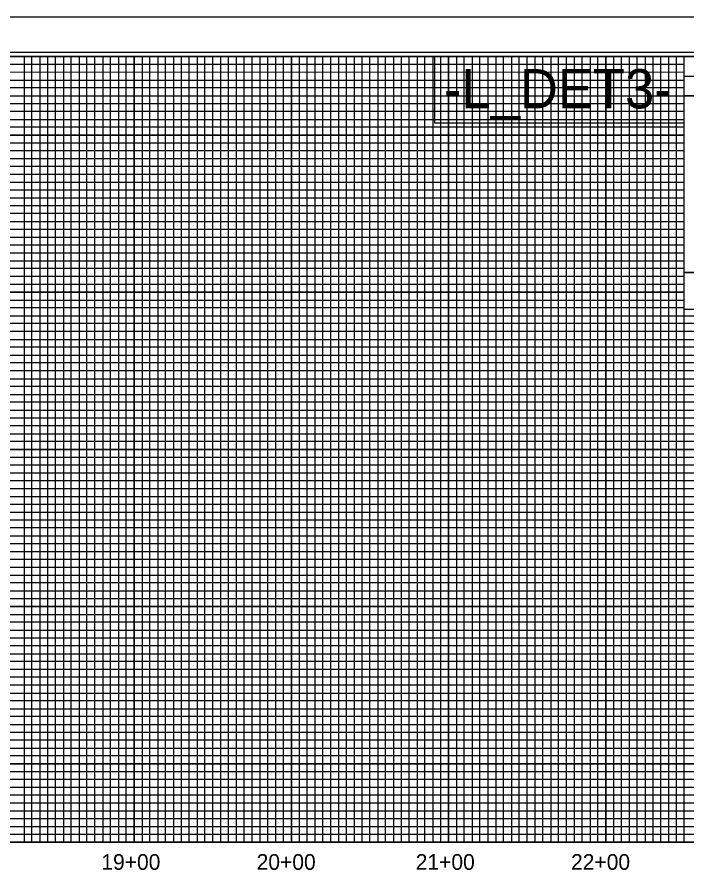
# Model space of a CAD drawing. Extents: x 497599 to 513368, y 404140 to 476034.
# Drawn here: x 506734 to 507160, y 439315 to 439861 of the extents above; entities that cross this region are included whole.
import ezdxf

# ---------------------------------------------------------------- set-up
doc = ezdxf.new("R2010")
doc.units = 0
for name, color, linetype in [('Exist Vertical Profile Vertical Axis Label', 7, 'Continuous'), ('Old_Level_1', 7, 'Continuous'), ('Prop Grid Mask', 7, 'Continuous'), ('Sheet Cutting Line CELL', 7, 'Continuous'), ('Sheet DOT Grid CELL', 7, 'Continuous'), ('Sheet Layout Profile Border Port 2', 7, 'Continuous'), ('Sheet Plot Border Inside CELL', 7, 'Continuous'), ('Sheet Plot Border Outside CELL', 7, 'Continuous'), ('Sheet Profile CELL', 7, 'Continuous'), ('Sheet Profile Grid Major CELL', 7, 'Continuous'), ('Sheet Profile Grid Middle CELL', 7, 'Continuous'), ('Sheet Profile Grid Minor CELL', 7, 'Continuous'), ('Sheet Sticker Exception Certification CELL', 7, 'Continuous')]:
    doc.layers.add(name, color=color, linetype=linetype)

msp = doc.modelspace()

# ---------------------------------------------------------------- linework, layer by layer
at = {"layer": 'Prop Grid Mask'}
msp.add_lwpolyline([(507158.63, 439836.14), (506999.77, 439836.14), (506999.77, 439793.82), (507158.63, 439793.82)], close=True, dxfattribs=at)
at = {"layer": 'Sheet Cutting Line CELL'}
msp.add_line((507375.68, 439861.14), (505691.68, 439861.14), dxfattribs=at)
at = {"layer": 'Sheet DOT Grid CELL'}
for p, q in [((506758.68, 439336.14), (506758.68, 439836.14)), ((506808.68, 439336.14), (506808.68, 439836.14)), ((506858.68, 439336.14), (506858.68, 439836.14)), ((506908.68, 439336.14), (506908.68, 439836.14)), ((506958.68, 439336.14), (506958.68, 439836.14)), ((507008.68, 439336.14), (507008.68, 439836.14)), ((507058.68, 439336.14), (507058.68, 439836.14)), ((507108.68, 439336.14), (507108.68, 439836.14)), ((507158.63, 439786.14), (505858.68, 439786.14)), ((507158.63, 439736.14), (505858.68, 439736.14)), ((507158.68, 439336.14), (507158.68, 439698.59)), ((507158.68, 439686.14), (505858.68, 439686.14)), ((507358.68, 439636.14), (505858.68, 439636.14)), ((507358.68, 439586.14), (505858.68, 439586.14)), ((507358.68, 439536.14), (505858.68, 439536.14)), ((507358.68, 439486.14), (505858.68, 439486.14)), ((507358.68, 439436.14), (505858.68, 439436.14)), ((507358.68, 439386.14), (505858.68, 439386.14))]:
    msp.add_line(p, q, dxfattribs=at)
at = {"layer": 'Sheet Layout Profile Border Port 2'}
msp.add_lwpolyline([(505908.68, 439836.14), (507308.68, 439836.14), (507308.68, 439336.14), (505908.68, 439336.14)], close=True, dxfattribs=at)
at = {"layer": 'Sheet Plot Border Inside CELL'}
msp.add_lwpolyline([(505704.68, 438783.59), (507371.18, 438783.59), (507371.18, 439838.69), (505704.68, 439838.69)], close=True, dxfattribs=at)
at = {"layer": 'Sheet Plot Border Outside CELL'}
msp.add_lwpolyline([(505691.68, 438761.14), (507375.68, 438761.14), (507375.68, 439861.14), (505691.68, 439861.14)], close=True, dxfattribs=at)
at = {"layer": 'Sheet Profile CELL'}
for p, q in [((507158.63, 439823.59), (507358.68, 439823.59)), ((505858.68, 439336.14), (507358.68, 439336.14))]:
    msp.add_line(p, q, dxfattribs=at)
for points in [[(507358.68, 439836.14), (505858.68, 439836.14), (505858.68, 438786.14), (507358.68, 438786.14)], [(507158.63, 439836.14), (507358.68, 439836.14), (507358.68, 439811.09), (507158.63, 439811.09)], [(507158.63, 439811.09), (507258.68, 439811.09), (507258.68, 439698.59), (507158.63, 439698.59)]]:
    msp.add_lwpolyline(points, close=True, dxfattribs=at)
at = {"layer": 'Sheet Profile Grid Major CELL'}
for points in [[(506708.68, 439336.14), (506758.68, 439336.14), (506758.68, 439836.14), (506808.68, 439836.14), (506808.68, 439336.14), (506858.68, 439336.14), (506858.68, 439836.14), (506908.68, 439836.14), (506908.68, 439336.14), (506958.68, 439336.14), (506958.68, 439836.14), (507008.68, 439836.14), (507008.68, 439336.14), (507058.68, 439336.14), (507058.68, 439836.14), (507108.68, 439836.14), (507108.68, 439336.14), (507158.68, 439336.14), (507158.68, 439836.14), (507184.98, 439836.14)], [(505858.68, 439786.14), (507158.68, 439786.14)], [(507158.68, 439736.14), (505858.68, 439736.14), (505858.68, 439686.14), (507158.68, 439686.14)], [(507358.68, 439636.14), (505858.68, 439636.14), (505858.68, 439586.14), (507358.68, 439586.14)], [(507358.68, 439536.14), (505858.68, 439536.14), (505858.68, 439486.14), (507358.68, 439486.14)], [(507358.68, 439436.14), (505858.68, 439436.14), (505858.68, 439436.14), (505858.68, 439386.14), (507358.68, 439386.14)]]:
    msp.add_lwpolyline(points, dxfattribs=at)
at = {"layer": 'Sheet Profile Grid Middle CELL'}
msp.add_line((505858.68, 439811.14), (507158.63, 439811.14), dxfattribs=at)
for points in [[(506733.68, 439336.14), (506783.68, 439336.14), (506783.68, 439836.14), (506833.68, 439836.14), (506833.68, 439336.14), (506883.68, 439336.14), (506883.68, 439836.14), (506933.68, 439836.14), (506933.68, 439336.14), (506983.68, 439336.14), (506983.68, 439836.14), (507033.68, 439836.14), (507033.68, 439336.14), (507083.68, 439336.14), (507083.68, 439836.14), (507133.68, 439836.14), (507133.68, 439336.14), (507183.68, 439336.14), (507183.68, 439675.09)], [(507158.68, 439761.14), (505858.68, 439761.14), (505858.68, 439711.14), (507158.68, 439711.14)], [(507358.68, 439661.14), (505858.68, 439661.14), (505858.68, 439611.14), (507183.68, 439611.14)], [(507358.68, 439561.14), (505858.68, 439561.14), (505858.68, 439511.14), (507358.68, 439511.14)], [(507358.68, 439461.14), (505858.68, 439461.14), (505858.68, 439411.14), (507358.68, 439411.14)], [(507358.68, 439361.14), (505858.68, 439361.14)]]:
    msp.add_lwpolyline(points, dxfattribs=at)
at = {"layer": 'Sheet Profile Grid Minor CELL'}
for p, q in [((505908.68, 439831.14), (507158.68, 439831.14)), ((507158.68, 439826.14), (505908.68, 439825.79)), ((505908.68, 439821.14), (507158.68, 439821.14)), ((507158.63, 439701.14), (505908.68, 439701.14)), ((507158.68, 439696.14), (505908.68, 439696.14)), ((507158.68, 439691.14), (505908.68, 439691.14)), ((505908.68, 439681.14), (507158.68, 439681.14)), ((507158.68, 439676.14), (505908.68, 439676.14)), ((505908.68, 439671.14), (507308.68, 439671.14)), ((507308.68, 439651.14), (505908.68, 439651.14)), ((505908.68, 439646.14), (507308.68, 439646.14)), ((507308.68, 439626.14), (505908.68, 439626.14)), ((505908.68, 439621.14), (507308.68, 439621.14)), ((507308.68, 439601.14), (505908.68, 439601.14)), ((505908.68, 439596.14), (507308.68, 439596.14)), ((507308.68, 439591.14), (505908.68, 439591.14)), ((505908.68, 439581.14), (507308.68, 439581.14)), ((507308.68, 439576.14), (505908.68, 439576.14)), ((505908.68, 439571.14), (507308.68, 439571.14)), ((507308.68, 439566.14), (505908.68, 439566.14)), ((505908.68, 439556.14), (507308.68, 439556.14)), ((507308.68, 439551.14), (505908.68, 439551.14)), ((505908.68, 439546.14), (507308.68, 439546.14)), ((507308.68, 439541.14), (505908.68, 439541.14)), ((505908.68, 439531.14), (507308.68, 439531.14)), ((507308.68, 439526.14), (505908.68, 439526.14)), ((505908.68, 439521.14), (507308.68, 439521.14)), ((507308.68, 439516.14), (505908.68, 439516.14)), ((505908.68, 439506.14), (507308.68, 439506.14)), ((507308.68, 439501.14), (505908.68, 439501.14)), ((505908.68, 439496.14), (507308.68, 439496.14)), ((507308.68, 439491.14), (505908.68, 439491.14)), ((505908.68, 439481.14), (507308.68, 439481.14)), ((507308.68, 439476.14), (505908.68, 439476.14)), ((505908.68, 439471.14), (507308.68, 439471.14)), ((507308.68, 439466.14), (505908.68, 439466.14)), ((505908.68, 439456.14), (507308.68, 439456.14)), ((507308.68, 439451.14), (505908.68, 439451.14)), ((507308.68, 439446.14), (505908.68, 439446.14)), ((507308.68, 439441.14), (505908.68, 439441.14)), ((505908.68, 439431.14), (507308.68, 439431.14)), ((507308.68, 439426.14), (505908.68, 439426.14)), ((505908.68, 439421.14), (507308.68, 439421.14)), ((507308.68, 439416.14), (505908.68, 439416.14)), ((505908.68, 439406.14), (507308.68, 439406.14)), ((507308.68, 439401.14), (505908.68, 439401.14)), ((505908.68, 439396.14), (507308.68, 439396.14)), ((507308.68, 439391.14), (505908.68, 439391.14)), ((505908.68, 439381.14), (507308.68, 439381.14)), ((507308.68, 439376.14), (505908.68, 439376.14)), ((505908.68, 439371.14), (507308.68, 439371.14)), ((507308.68, 439366.14), (505908.68, 439366.14)), ((505908.68, 439356.14), (507308.68, 439356.14)), ((507308.68, 439351.14), (505908.68, 439351.14)), ((505908.68, 439346.14), (507308.68, 439346.14))]:
    msp.add_line(p, q, dxfattribs=at)
for points in [[(506728.68, 439836.14), (506738.68, 439836.14), (506738.68, 439336.14), (506743.68, 439336.14)], [(506743.68, 439336.14), (506743.68, 439836.14), (506748.68, 439836.14), (506748.68, 439336.14), (506753.68, 439336.14), (506753.68, 439836.14), (506763.68, 439836.14), (506763.68, 439336.14), (506768.68, 439336.14), (506768.68, 439836.14), (506773.68, 439836.14), (506773.68, 439336.14), (506778.68, 439336.14), (506778.68, 439836.14), (506788.68, 439836.14), (506788.68, 439336.14), (506793.68, 439336.14), (506793.68, 439836.14), (506798.68, 439836.14), (506798.68, 439336.14), (506803.68, 439336.14), (506803.68, 439836.14), (506813.68, 439836.14), (506813.68, 439336.14), (506818.68, 439336.14), (506818.68, 439836.14), (506823.68, 439836.14), (506823.68, 439336.14), (506828.68, 439336.14), (506828.68, 439836.14), (506838.68, 439836.14), (506838.68, 439336.14), (506843.68, 439336.14), (506843.68, 439836.14), (506848.68, 439836.14), (506848.68, 439336.14), (506853.68, 439336.14), (506853.68, 439836.14), (506863.68, 439836.14), (506863.68, 439336.14), (506868.68, 439336.14), (506868.68, 439836.14), (506873.68, 439836.14), (506873.68, 439336.14), (506878.68, 439336.14), (506878.68, 439836.14), (506888.68, 439836.14), (506888.68, 439336.14), (506893.68, 439336.14), (506893.68, 439836.14), (506898.68, 439836.14), (506898.68, 439336.14), (506903.68, 439336.14), (506903.68, 439836.14), (506913.68, 439836.14), (506913.68, 439336.14), (506918.68, 439336.14), (506918.68, 439836.14), (506923.68, 439836.14), (506923.68, 439336.14), (506928.68, 439336.14), (506928.68, 439836.14), (506938.68, 439836.14), (506938.68, 439336.14), (506943.68, 439336.14), (506943.68, 439836.14), (506948.68, 439836.14), (506948.68, 439336.14), (506953.68, 439336.14), (506953.68, 439836.14), (506963.68, 439836.14), (506963.68, 439336.14), (506968.68, 439336.14), (506968.68, 439836.14), (506973.68, 439836.14), (506973.68, 439336.14), (506978.68, 439336.14), (506978.68, 439836.14), (506988.68, 439836.14), (506988.68, 439336.14), (506993.68, 439336.14), (506993.68, 439836.14), (506998.68, 439836.14), (506998.68, 439336.14), (507003.68, 439336.14), (507003.68, 439836.14), (507013.68, 439836.14), (507013.68, 439336.14), (507018.68, 439336.14), (507018.68, 439836.14), (507023.68, 439836.14), (507023.68, 439336.14), (507028.68, 439336.14), (507028.68, 439836.14), (507038.68, 439836.14), (507038.68, 439336.14), (507043.68, 439336.14), (507043.68, 439836.14), (507048.68, 439836.14), (507048.68, 439336.14)], [(507048.68, 439336.14), (507053.68, 439336.14), (507053.68, 439836.14), (507063.68, 439836.14), (507063.68, 439336.14), (507068.68, 439336.14), (507068.68, 439836.14), (507073.68, 439836.14), (507073.68, 439336.14), (507078.68, 439336.14), (507078.68, 439836.14), (507088.68, 439836.14), (507088.68, 439336.14), (507093.68, 439336.14), (507093.68, 439836.14), (507098.68, 439836.14), (507098.68, 439336.14), (507103.68, 439336.14), (507103.68, 439836.14), (507113.68, 439836.14), (507113.68, 439336.14), (507118.68, 439336.14), (507118.68, 439836.14), (507123.68, 439836.14), (507123.68, 439336.14), (507128.68, 439336.14), (507128.68, 439836.14), (507138.68, 439836.14), (507138.68, 439336.14), (507143.68, 439336.14), (507143.68, 439836.14), (507148.68, 439836.14), (507148.68, 439336.14), (507153.68, 439336.14), (507153.68, 439836.14), (507163.68, 439836.14)], [(507158.68, 439816.14), (505908.68, 439816.14), (505908.68, 439806.14), (507158.68, 439806.14)], [(507158.63, 439801.14), (505908.68, 439801.14), (505908.68, 439796.14), (507158.68, 439796.14)], [(507158.68, 439791.14), (505908.68, 439791.14), (505908.68, 439781.14), (507158.68, 439781.14)], [(507158.68, 439776.14), (505908.68, 439776.14), (505908.68, 439771.14), (507158.68, 439771.14)], [(507158.68, 439766.14), (505908.68, 439766.14), (505908.68, 439756.14), (507158.68, 439756.14)], [(507158.68, 439751.14), (505908.68, 439751.14), (505908.68, 439746.14), (507158.68, 439746.14)], [(507158.68, 439741.14), (505908.68, 439741.14), (505908.68, 439731.14), (507158.68, 439731.14)], [(507158.68, 439726.04), (505908.78, 439726.04), (505908.78, 439721.14), (507158.68, 439721.14)], [(507158.68, 439716.14), (505908.68, 439716.14), (505908.68, 439706.14), (507158.68, 439706.14)], [(507308.68, 439666.14), (505908.68, 439666.14), (505908.68, 439656.14), (507308.68, 439656.14)], [(507308.68, 439641.14), (505908.68, 439641.14), (505908.68, 439631.14), (507308.68, 439631.14)], [(507308.68, 439616.14), (505908.68, 439616.14), (505908.68, 439606.14), (507308.68, 439606.14)], [(507308.68, 439341.14), (505908.68, 439341.14)]]:
    msp.add_lwpolyline(points, dxfattribs=at)
at = {"layer": 'Sheet Sticker Exception Certification CELL'}
for p, q in [((507158.63, 439675.09), (507158.63, 439698.59)), ((507158.63, 439698.59), (507358.67, 439698.59)), ((507158.63, 439675.09), (507158.63, 439698.59)), ((507158.63, 439698.59), (507358.67, 439698.59)), ((507358.67, 439675.09), (507158.63, 439675.09)), ((507358.67, 439675.09), (507158.63, 439675.09))]:
    msp.add_line(p, q, dxfattribs=at)

# ---------------------------------------------------------------- texts
at = {"layer": 'Exist Vertical Profile Vertical Axis Label'}
for s, p in [('19+00', (506787.81, 439318.64)), ('20+00', (506886.61, 439318.64)), ('21+00', (506987.81, 439318.64)), ('22+00', (507086.61, 439318.64))]:
    msp.add_text(s, height=10, dxfattribs=at).set_placement(p)
at = {"layer": 'Old_Level_1'}
msp.add_text('-L_DET3-', height=25, dxfattribs=at).set_placement((507005.77, 439803.11))

doc.saveas('drawing.dxf')
